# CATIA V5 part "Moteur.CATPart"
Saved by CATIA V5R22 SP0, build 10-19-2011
Part number: Moteur
Bounding box of the stored display mesh (mm): x -21.15 to 21.15, y -21.15 to 21.15, z 0 to 64
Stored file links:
  U:\S9A\PER\CAO\Assemblage\Cadre\Chariot_X\Moteur.CATPart
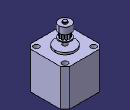
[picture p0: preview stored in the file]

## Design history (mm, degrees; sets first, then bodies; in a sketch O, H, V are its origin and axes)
Body1 (main body)
  Sketch1 on xy-plane, origin (0, 0, 0), H (1, 0, 0), V (0, 1, 0)
    point P1 (-21.15, 21.15)
    line L1 (-21.15, 21.15) -> (21.15, 21.15)
    line L2 (21.15, 21.15) -> (21.15, -21.15)
    line L3 (21.15, -21.15) -> (-21.15, -21.15)
    line L4 (-21.15, -21.15) -> (-21.15, 21.15)
    point P2 (21.15, 21.15)
    point P3 (21.15, -21.15)
    point P4 (-21.15, -21.15)
    length L1 = 42.3
    length L2 = 42.3
    horizontal: L1 H, L3 H
    vertical: L2 V, L4 V
    equidistance: P4 P2 O, P3 P1 O
  Pad1: profile Sketch1, direction (0, 0, 1), length 40
  Sketch2 on end face of Pad1, origin (0, 0, 40), H (1, 0, 0), V (0, 1, 0)
    circle A1 centre (0, 0) radius 2.5
    radius A1 = 2.5
  Pad2: profile Sketch2, direction (0, 0, 1), length 24
  Sketch3 on end face of Pad1, origin (0, 0, 40), H (1, 0, 0), V (0, 1, 0)
    circle A1 centre (0, 0) radius 11
    radius A1 = 11
  Pad3: profile Sketch3, direction (0, 0, 1), length 2
  Chamfer1: length 5, angle 45, on edge [face of Pad1 from Sketch1.L1 | face of Pad1 from Sketch1.L2]; edge [face of Pad1 from Sketch1.L2 | face of Pad1 from Sketch1.L3]; edge [face of Pad1 from Sketch1.L4 | face of Pad1 from Sketch1.L1]; edge [face of Pad1 from Sketch1.L3 | face of Pad1 from Sketch1.L4]
  Plane1: type Offset, RefPlane end face of Pad2, Offset 15
  Sketch4 on Plane1, origin (0, 0, 49), H (1, 0, 0), V (0, -1, 0)
    circle A1 centre (0, 0) radius 6.5
    radius A1 = 6.5
  Pad4: profile Sketch4, direction (0, 0, -1), length 1
  Sketch5 on start face of Pad4, origin (0, 0, 49), H (1, 0, 0), V (0, 1, 0)
    circle A1 centre (0, 0) radius 5
    radius A1 = 5
  Pad5: profile Sketch5, direction (0, 0, 1), length 6.5
  Sketch6 on end face of Pad5, origin (0, 0, 55.5), H (1, 0, 0), V (0, 1, 0)
    line L1 (3, 0) -> (5.5981, 1.5)
    point P1 (3, 0)
    line L2 (5.5981, 1.5) -> (5.5981, -1.5)
    line L3 (5.5981, -1.5) -> (3, 0)
    reference intersected line E1 through (0, 0) direction (0, 1) from yz-plane
    distance P1 E1 = 3
    length L1 = 3
    length L3 = 3
    length L2 = 3
    coincidence: P1 H
    vertical: L2 V
  Pocket1: profile Sketch6, direction (0, 0, -1), length 6.5
  CircPattern1: of Pocket1, instances 9, angular step 40, axis from end face of Pad5
  Sketch7 on end face of Pad5, origin (0, 0, 55.5), H (1, 0, 0), V (0, 1, 0)
    circle A1 centre (0, 0) radius 6.5
    radius A1 = 6.5
  Pad6: profile Sketch7, direction (0, 0, 1), length 7
  Fillet1: radius 0.5, on edge [face of Pad2 from Sketch2.A1 | end face of Pad2]
  Sketch8 on end face of Pad1, origin (-13.6522, 14.0779, 40), H (1, 0, 0), V (0, 1, 0)
    point P1 (-1.8478, 1.4221)
    reference projected line E1 (-7.4978, 7.0721) -> (-7.4978, -35.2279) from edge [face of Pad1 from Sketch1.L4 | end face of Pad1]
    reference projected line E2 (34.8022, 7.0721) -> (-7.4978, 7.0721) from edge [face of Pad1 from Sketch1.L1 | end face of Pad1]
    distance P1 E1 = 5.65
    distance P1 E2 = 5.65
  Hole1: placed by Sketch8, at (-15.5, 15.5, 40) direction (0, 0, -1), diameter 6, depth 4.5
  RectPattern1: of Hole1, direction 1 instances 2, spacing 31, along end face of Pad1, direction 2 instances 2, spacing 31, along end face of Pad1 reversed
